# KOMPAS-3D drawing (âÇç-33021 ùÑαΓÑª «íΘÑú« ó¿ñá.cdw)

Views: Вид 1
Referenced files in D:\Вадик\Автомобили\: Чертёж-ГАЗель.cdw
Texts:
  КПАВ 2007.049.01.00 ВО
  ГАЗ-33021 Чертеж общего вида
  Вадя
  133 1 134 1 135 1 136 0 50 1|SPDS|133 1 134 1 135 1 136 0 50 1
  125 1 126 1 127 1 128 0 50 1|SPDS|125 1 126 1 127 1 128 0 50 1
  129 1 130 1 131 1 132 0 50 1|SPDS|129 1 130 1 131 1 132 0 50 1
  Слой 1
  h бак с топл. =
  h задн. мост. =
  h рамы =
  h кпп =
  h ц.т. без груза =
  h двиг. =
  h каб. =
  h пас. =
  h груз. =
  lкпп =
  lкаб =
  lпас. =
  lбак с топл. =
  lзадн. мост =
  lгруз. =
  lдвиг. =
  lрад. =
  lц.т. с грузом =
  h ц.т. с грузом =
  lц.т. без груза =
  В задн. колеи =
  В пер. колеи =
  lрамы =
  h клир. =
  Грузоподъёмность автомобиля, кг.                                1799
  Собственная масса, кг.                                           2016
  на заднюю ось, кг.                                                        899
  Полная масса,, кг.                                                   4040
  на переднюю ось, кг.                                                    1365
  на заднюю ось, кг.                                                      2675
  Число мест                                                               3
  Тип двигателя                  бензиновый, карбюраторный,рядный,
  4-цилиндровый, 4-тактный, 16-клапанный
  Максимальная скорость движения, км/ч                          120
  Максимальная мощность двигателя, кВт/(об/мин)      166/4550
  Максимальный крутящий момент, Нм/(об/мин)          440/2249
  Передаточные отношения:   - 2.35;   - 1.65;   - 1.16;   - 0.82;
  Symbol type A
  ЗХ - 3.51.
  Шины                                              175R16C модель Я462
  Крапивный В.И.
  Рогозина Т.А.
  Кафедра АТ
  группа АВ-41д
  ГАЗ-33021
  Чертеж общего вида
  КПАВ 2007.049.00 ВО-
Dimensions and other numbers on the sheet: 0; 1; 2; 3; 4; 5; 6; 7; 8; 9; 2900; 990; 2340; 2612; 1966; 467; 316; 552; 673; 738; 814; 947; 1168; 1716; 165; 242; 646; 1769; 2865; 398; 774; 1920; 1148; 2545; 1293; 22 25'; 21 48'; 1560; 1700; 5440; 1773; 129; 1:15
